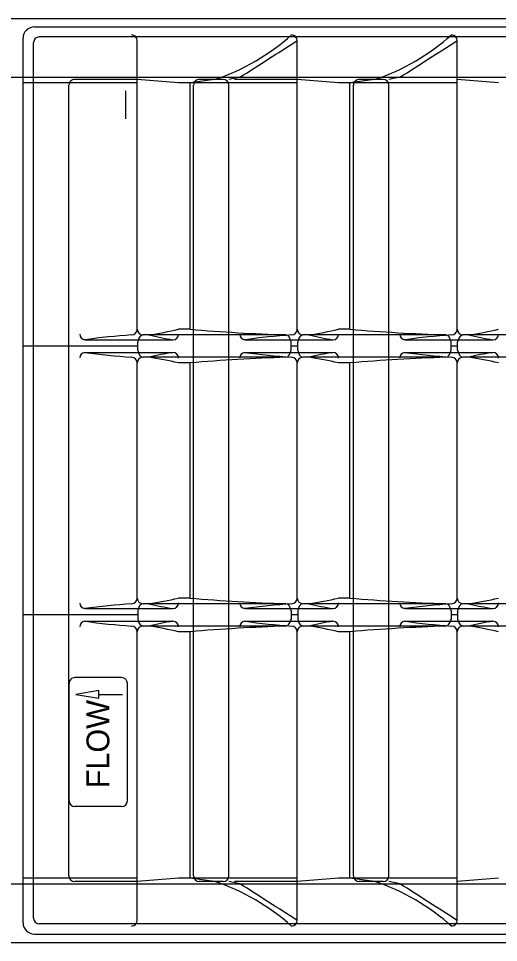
# Model space of a CAD drawing. Extents: x 0.9 to 8.1, y 0.4 to 10.5.
# Drawn here: x 4.67 to 5.041, y 9.231 to 9.946 of the extents above; entities that cross this region are included whole.
import ezdxf

# ---------------------------------------------------------------- set-up
doc = ezdxf.new("R2010")
doc.units = 0
doc.layers.add('DETL-LINE', color=7, linetype='Continuous')
doc.layers.add('DETL-NOTE', color=7, linetype='Continuous')

msp = doc.modelspace()

# ---------------------------------------------------------------- linework, layer by layer
at = {"layer": 'DETL-LINE'}
for p, q in [((3.82262, 9.94588), (5.52014, 9.94588)), ((4.68243, 9.93938), (5.51572, 9.93938)), ((4.67359, 9.24584), (4.67359, 9.93071)), ((4.68174, 9.24951), (4.68174, 9.92726)), ((5.51198, 9.93159), (4.68617, 9.93159)), ((4.762, 9.70529), (4.762, 9.92883)), ((4.88578, 9.70529), (4.88578, 9.92883)), ((5.00956, 9.70529), (5.00956, 9.92883)), ((3.86903, 9.90037), (5.47373, 9.90037)), ((4.762, 9.89868), (4.71355, 9.89868)), ((4.79394, 9.89604), (4.762, 9.89868)), ((4.82182, 9.89862), (4.80278, 9.89604)), ((4.82848, 9.89868), (4.80994, 9.89868)), ((4.84135, 9.90037), (4.8329, 9.89862)), ((4.88578, 9.89868), (4.83732, 9.89868)), ((4.91772, 9.89604), (4.88578, 9.89868)), ((4.94559, 9.89862), (4.92656, 9.89604)), ((4.95226, 9.89868), (4.93372, 9.89868)), ((4.96513, 9.90037), (4.95668, 9.89862)), ((5.0415, 9.89604), (5.00956, 9.89868)), ((4.762, 9.89604), (4.67359, 9.89604)), ((4.70913, 9.28221), (4.70913, 9.89435)), ((4.80278, 9.89604), (4.79394, 9.89604)), ((4.88578, 9.89604), (4.80278, 9.89604)), ((4.80278, 9.70531), (4.80278, 9.89604)), ((4.80552, 9.28221), (4.80552, 9.89435)), ((4.8329, 9.28221), (4.8329, 9.89435)), ((4.92656, 9.89604), (4.91772, 9.89604)), ((4.92656, 9.70531), (4.92656, 9.89604)), ((5.00956, 9.89604), (4.92656, 9.89604)), ((4.9293, 9.28221), (4.9293, 9.89435)), ((4.95668, 9.28221), (4.95668, 9.89435)), ((4.75295, 9.88992), (4.75295, 9.86809)), ((4.87694, 9.70095), (4.76642, 9.70095)), ((4.80278, 9.70531), (4.79394, 9.70531)), ((5.00072, 9.70095), (4.8902, 9.70095)), ((4.92656, 9.70531), (4.91772, 9.70531)), ((5.12449, 9.70095), (5.01398, 9.70095)), ((4.76233, 9.69231), (4.67359, 9.69231)), ((4.72136, 9.6972), (4.78952, 9.6972)), ((4.76233, 9.68906), (4.76233, 9.69556)), ((4.84514, 9.6972), (4.9133, 9.6972)), ((4.88103, 9.68906), (4.88103, 9.69556)), ((4.8861, 9.69231), (4.88103, 9.69231)), ((4.8861, 9.68906), (4.8861, 9.69556)), ((4.96892, 9.6972), (5.03708, 9.6972)), ((5.00481, 9.68906), (5.00481, 9.69556)), ((5.00988, 9.69231), (5.00481, 9.69231)), ((5.00988, 9.68906), (5.00988, 9.69556)), ((4.72136, 9.68742), (4.78952, 9.68742)), ((4.84514, 9.68742), (4.9133, 9.68742)), ((4.96892, 9.68742), (5.03708, 9.68742)), ((4.762, 9.49722), (4.762, 9.67934)), ((4.87694, 9.68367), (4.76642, 9.68367)), ((4.80278, 9.67931), (4.79394, 9.67931)), ((4.80278, 9.49725), (4.80278, 9.67931)), ((4.88578, 9.49722), (4.88578, 9.67934)), ((5.00072, 9.68367), (4.8902, 9.68367)), ((4.92656, 9.67931), (4.91772, 9.67931)), ((4.92656, 9.49725), (4.92656, 9.67931)), ((5.00956, 9.49722), (5.00956, 9.67934)), ((5.12449, 9.68367), (5.01398, 9.68367)), ((4.87694, 9.49289), (4.76642, 9.49289)), ((4.80278, 9.49725), (4.79394, 9.49725)), ((5.00072, 9.49289), (4.8902, 9.49289)), ((4.92656, 9.49725), (4.91772, 9.49725)), ((5.12449, 9.49289), (5.01398, 9.49289)), ((4.76233, 9.48425), (4.67359, 9.48425)), ((4.72136, 9.48914), (4.78952, 9.48914)), ((4.76233, 9.4875), (4.76233, 9.481)), ((4.84514, 9.48914), (4.9133, 9.48914)), ((4.88103, 9.4875), (4.88103, 9.481)), ((4.8861, 9.48425), (4.88103, 9.48425)), ((4.8861, 9.4875), (4.8861, 9.481)), ((4.96892, 9.48914), (5.03708, 9.48914)), ((5.00481, 9.4875), (5.00481, 9.481)), ((5.00988, 9.48425), (5.00481, 9.48425)), ((5.00988, 9.4875), (5.00988, 9.481)), ((4.72136, 9.47936), (4.78952, 9.47936)), ((4.84514, 9.47936), (4.9133, 9.47936)), ((4.96892, 9.47936), (5.03708, 9.47936)), ((4.762, 9.24773), (4.762, 9.47127)), ((4.87694, 9.47561), (4.76642, 9.47561)), ((4.80278, 9.47124), (4.79394, 9.47124)), ((4.80278, 9.28052), (4.80278, 9.47124)), ((4.88578, 9.24773), (4.88578, 9.47127)), ((5.00072, 9.47561), (4.8902, 9.47561)), ((4.92656, 9.47124), (4.91772, 9.47124)), ((4.92656, 9.28052), (4.92656, 9.47124)), ((5.00956, 9.24773), (5.00956, 9.47127)), ((5.12449, 9.47561), (5.01398, 9.47561)), ((4.762, 9.28052), (4.67359, 9.28052)), ((4.762, 9.27788), (4.71355, 9.27788)), ((4.79394, 9.28052), (4.762, 9.27788)), ((4.80278, 9.28052), (4.79394, 9.28052)), ((4.88578, 9.28052), (4.80278, 9.28052)), ((4.82182, 9.27794), (4.80278, 9.28052)), ((4.82848, 9.27788), (4.80994, 9.27788)), ((4.84135, 9.27619), (4.8329, 9.27794)), ((4.88578, 9.27788), (4.83732, 9.27788)), ((4.91772, 9.28052), (4.88578, 9.27788)), ((4.92656, 9.28052), (4.91772, 9.28052)), ((5.00956, 9.28052), (4.92656, 9.28052)), ((4.94559, 9.27794), (4.92656, 9.28052)), ((4.95226, 9.27788), (4.93372, 9.27788)), ((4.96513, 9.27619), (4.95668, 9.27794)), ((5.0415, 9.28052), (5.00956, 9.27788)), ((3.86903, 9.27619), (5.47373, 9.27619)), ((5.51198, 9.24517), (4.68617, 9.24517)), ((4.68243, 9.23717), (5.51572, 9.23717)), ((3.82262, 9.23067), (5.52014, 9.23067))]:
    msp.add_line(p, q, dxfattribs=at)
for centre, major_axis, ratio, start_param, end_param in [((4.68243, 9.93071), (0.00884, 0), 0.98054, 1.570796, 3.141593), ((4.68617, 9.92726), (0.00442, 0), 0.98054, 1.570796, 3.141593), ((4.75758, 9.92883), (0.00442, 0), 0.98054, 0, 1.570796), ((4.76845, 10.05367), (0.16689, 0), 0.98054, 5.037871, 5.45546), ((-5.57268, 25.57897), (19.08204, 0), 0.98054, 5.289674, 5.292455), ((4.88136, 9.92883), (0.00442, 0), 0.98054, 0, 1.570796), ((4.89223, 10.05367), (0.16689, 0), 0.98054, 5.037871, 5.45546), ((-5.4489, 25.57897), (19.08204, 0), 0.98054, 5.289674, 5.292455), ((5.00514, 9.92883), (0.00442, 0), 0.98054, 0, 1.570796), ((4.71355, 9.89435), (0.00442, 0), 0.98054, 1.570796, 3.141593), ((4.80994, 9.89435), (0.00442, 0), 0.98054, 1.570796, 3.141593), ((4.82848, 9.89435), (0.00442, 0), 0.98054, 0, 1.570796), ((4.93372, 9.89435), (0.00442, 0), 0.98054, 1.570796, 3.141593), ((4.95226, 9.89435), (0.00442, 0), 0.98054, 0, 1.570796), ((4.72199, 9.70149), (0.00442, 0), 0.98054, 3.141593, 4.569086), ((4.79758, 9.15999), (0.55314, 0), 0.98054, 1.643175, 1.709028), ((4.75758, 9.70529), (0.00442, 0), 0.98054, 4.712389, 6.283185), ((4.76642, 9.70529), (0.00442, 0), 0.98054, 3.141593, 4.712389), ((4.76642, 9.69231), (0, -0.00864), 0.511537, 3.112642, 4.326712), ((4.7212, 10.01464), (0.32374, 0), 0.98054, 4.866324, 4.938996), ((4.82826, 9.92906), (0.23962, 0), 0.98054, 4.470431, 4.550015), ((4.78952, 9.70153), (0.00442, 0), 0.98054, 4.712389, 6.283185), ((4.93221, 11.21264), (1.54268, 0), 0.98054, 4.628392, 4.676553), ((4.84577, 9.70149), (0.00442, 0), 0.98054, 3.141593, 4.569086), ((4.92136, 9.15999), (0.55314, 0), 0.98054, 1.643175, 1.709028), ((4.87694, 9.69231), (0, 0.00864), 0.511537, 5.098066, 6.283185), ((4.88136, 9.70529), (0.00442, 0), 0.98054, 4.712389, 6.283185), ((4.8902, 9.70529), (0.00442, 0), 0.98054, 3.141593, 4.712389), ((4.8902, 9.69231), (0, -0.00864), 0.511537, 3.112642, 4.326712), ((4.84498, 10.01464), (0.32374, 0), 0.98054, 4.866324, 4.938996), ((4.95204, 9.92906), (0.23962, 0), 0.98054, 4.470431, 4.550015), ((4.9133, 9.70153), (0.00442, 0), 0.98054, 4.712389, 6.283185), ((5.05599, 11.21264), (1.54268, 0), 0.98054, 4.628392, 4.676553), ((4.96955, 9.70149), (0.00442, 0), 0.98054, 3.141593, 4.569086), ((5.04514, 9.15999), (0.55314, 0), 0.98054, 1.643175, 1.709028), ((5.00072, 9.69231), (0, 0.00864), 0.511537, 5.098066, 6.283185), ((5.00514, 9.70529), (0.00442, 0), 0.98054, 4.712389, 6.283185), ((5.01398, 9.70529), (0.00442, 0), 0.98054, 3.141593, 4.712389), ((5.01398, 9.69231), (0, -0.00864), 0.511537, 3.112642, 4.326712), ((4.96876, 10.01464), (0.32374, 0), 0.98054, 4.866324, 4.938996), ((5.07581, 9.92906), (0.23962, 0), 0.98054, 4.470431, 4.550015), ((5.03708, 9.70153), (0.00442, 0), 0.98054, 4.712389, 6.283185), ((4.72199, 9.68313), (0.00442, 0), 0.98054, 1.714099, 3.141593), ((4.79758, 10.22463), (0.55314, 0), 0.98054, 4.574158, 4.64001), ((4.76642, 9.69231), (0, -0.00864), 0.511537, 5.098066, 6.283185), ((4.82826, 9.45555), (0.23962, 0), 0.98054, 1.733171, 1.812754), ((4.78952, 9.68309), (0.00442, 0), 0.98054, 0, 1.570796), ((4.84577, 9.68313), (0.00442, 0), 0.98054, 1.714099, 3.141593), ((4.92136, 10.22463), (0.55314, 0), 0.98054, 4.574158, 4.64001), ((4.87694, 9.69231), (0, 0.00864), 0.511537, 3.112642, 4.326712), ((4.8902, 9.69231), (0, -0.00864), 0.511537, 5.098066, 6.283185), ((4.95204, 9.45555), (0.23962, 0), 0.98054, 1.733171, 1.812754), ((4.9133, 9.68309), (0.00442, 0), 0.98054, 0, 1.570796), ((4.96955, 9.68313), (0.00442, 0), 0.98054, 1.714099, 3.141593), ((5.04514, 10.22463), (0.55314, 0), 0.98054, 4.574158, 4.64001), ((5.00072, 9.69231), (0, 0.00864), 0.511537, 3.112642, 4.326712), ((5.01398, 9.69231), (0, -0.00864), 0.511537, 5.098066, 6.283185), ((5.07581, 9.45555), (0.23962, 0), 0.98054, 1.733171, 1.812754), ((5.03708, 9.68309), (0.00442, 0), 0.98054, 0, 1.570796), ((4.75758, 9.67934), (0.00442, 0), 0.98054, 0, 1.570796), ((4.76642, 9.67934), (0.00442, 0), 0.98054, 1.570796, 3.141593), ((4.7212, 9.36998), (0.32374, 0), 0.98054, 1.344189, 1.416861), ((4.93221, 8.17197), (1.54268, 0), 0.98054, 1.606632, 1.654793), ((4.88136, 9.67934), (0.00442, 0), 0.98054, 0, 1.570796), ((4.8902, 9.67934), (0.00442, 0), 0.98054, 1.570796, 3.141593), ((4.84498, 9.36998), (0.32374, 0), 0.98054, 1.344189, 1.416861), ((5.05599, 8.17197), (1.54268, 0), 0.98054, 1.606632, 1.654793), ((5.00514, 9.67934), (0.00442, 0), 0.98054, 0, 1.570796), ((5.01398, 9.67934), (0.00442, 0), 0.98054, 1.570796, 3.141593), ((4.96876, 9.36998), (0.32374, 0), 0.98054, 1.344189, 1.416861), ((4.72199, 9.49343), (0.00442, 0), 0.98054, 3.141593, 4.569086), ((4.79758, 8.95193), (0.55314, 0), 0.98054, 1.643175, 1.709028), ((4.75758, 9.49722), (0.00442, 0), 0.98054, 4.712389, 6.283185), ((4.76642, 9.49722), (0.00442, 0), 0.98054, 3.141593, 4.712389), ((4.76642, 9.48425), (0, 0.00864), 0.511537, 0, 1.185119), ((4.7212, 9.80657), (0.32374, 0), 0.98054, 4.866324, 4.938996), ((4.82826, 9.721), (0.23962, 0), 0.98054, 4.470431, 4.550015), ((4.78952, 9.49347), (0.00442, 0), 0.98054, 4.712389, 6.283185), ((4.93221, 11.00458), (1.54268, 0), 0.98054, 4.628392, 4.676553), ((4.84577, 9.49343), (0.00442, 0), 0.98054, 3.141593, 4.569086), ((4.92136, 8.95193), (0.55314, 0), 0.98054, 1.643175, 1.709028), ((4.87694, 9.48425), (0, 0.00864), 0.511537, 5.098066, 6.283185), ((4.88136, 9.49722), (0.00442, 0), 0.98054, 4.712389, 6.283185), ((4.8902, 9.49722), (0.00442, 0), 0.98054, 3.141593, 4.712389), ((4.8902, 9.48425), (0, 0.00864), 0.511537, 0, 1.185119), ((4.84498, 9.80657), (0.32374, 0), 0.98054, 4.866324, 4.938996), ((4.95204, 9.721), (0.23962, 0), 0.98054, 4.470431, 4.550015), ((4.9133, 9.49347), (0.00442, 0), 0.98054, 4.712389, 6.283185), ((5.05599, 11.00458), (1.54268, 0), 0.98054, 4.628392, 4.676553), ((4.96955, 9.49343), (0.00442, 0), 0.98054, 3.141593, 4.569086), ((5.04514, 8.95193), (0.55314, 0), 0.98054, 1.643175, 1.709028), ((5.00072, 9.48425), (0, 0.00864), 0.511537, 5.098066, 6.283185), ((5.00514, 9.49722), (0.00442, 0), 0.98054, 4.712389, 6.283185), ((5.01398, 9.49722), (0.00442, 0), 0.98054, 3.141593, 4.712389), ((5.01398, 9.48425), (0, 0.00864), 0.511537, 0, 1.185119), ((4.96876, 9.80657), (0.32374, 0), 0.98054, 4.866324, 4.938996), ((5.07581, 9.721), (0.23962, 0), 0.98054, 4.470431, 4.550015), ((5.03708, 9.49347), (0.00442, 0), 0.98054, 4.712389, 6.283185), ((4.72199, 9.47507), (0.00442, 0), 0.98054, 1.714099, 3.141593), ((4.79758, 10.01657), (0.55314, 0), 0.98054, 4.574158, 4.64001), ((4.76642, 9.48425), (0, 0.00864), 0.511537, 1.956474, 3.170543), ((4.82826, 9.24749), (0.23962, 0), 0.98054, 1.733171, 1.812754), ((4.78952, 9.47502), (0.00442, 0), 0.98054, 0, 1.570796), ((4.84577, 9.47507), (0.00442, 0), 0.98054, 1.714099, 3.141593), ((4.92136, 10.01657), (0.55314, 0), 0.98054, 4.574158, 4.64001), ((4.87694, 9.48425), (0, 0.00864), 0.511537, 3.112642, 4.326712), ((4.8902, 9.48425), (0, 0.00864), 0.511537, 1.956474, 3.170543), ((4.95204, 9.24749), (0.23962, 0), 0.98054, 1.733171, 1.812754), ((4.9133, 9.47502), (0.00442, 0), 0.98054, 0, 1.570796), ((4.96955, 9.47507), (0.00442, 0), 0.98054, 1.714099, 3.141593), ((5.04514, 10.01657), (0.55314, 0), 0.98054, 4.574158, 4.64001), ((5.00072, 9.48425), (0, 0.00864), 0.511537, 3.112642, 4.326712), ((5.01398, 9.48425), (0, 0.00864), 0.511537, 1.956474, 3.170543), ((5.07581, 9.24749), (0.23962, 0), 0.98054, 1.733171, 1.812754), ((5.03708, 9.47502), (0.00442, 0), 0.98054, 0, 1.570796), ((4.75758, 9.47127), (0.00442, 0), 0.98054, 0, 1.570796), ((4.76642, 9.47127), (0.00442, 0), 0.98054, 1.570796, 3.141593), ((4.7212, 9.16192), (0.32374, 0), 0.98054, 1.344189, 1.416861), ((4.93221, 7.96391), (1.54268, 0), 0.98054, 1.606632, 1.654793), ((4.88136, 9.47127), (0.00442, 0), 0.98054, 0, 1.570796), ((4.8902, 9.47127), (0.00442, 0), 0.98054, 1.570796, 3.141593), ((4.84498, 9.16192), (0.32374, 0), 0.98054, 1.344189, 1.416861), ((5.05599, 7.96391), (1.54268, 0), 0.98054, 1.606632, 1.654793), ((5.00514, 9.47127), (0.00442, 0), 0.98054, 0, 1.570796), ((5.01398, 9.47127), (0.00442, 0), 0.98054, 1.570796, 3.141593), ((4.96876, 9.16192), (0.32374, 0), 0.98054, 1.344189, 1.416861), ((4.71355, 9.28221), (0.00442, 0), 0.98054, 3.141593, 4.712389), ((4.80994, 9.28221), (0.00442, 0), 0.98054, 3.141593, 4.712389), ((4.76845, 9.12289), (0.16689, 0), 0.98054, 0.827725, 1.245314), ((4.82848, 9.28221), (0.00442, 0), 0.98054, 4.712389, 6.283185), ((4.93372, 9.28221), (0.00442, 0), 0.98054, 3.141593, 4.712389), ((4.89223, 9.12289), (0.16689, 0), 0.98054, 0.827725, 1.245314), ((4.95226, 9.28221), (0.00442, 0), 0.98054, 4.712389, 6.283185), ((-5.57268, -6.40241), (19.08204, 0), 0.98054, 0.990731, 0.993512), ((-5.4489, -6.40241), (19.08204, 0), 0.98054, 0.990731, 0.993512), ((4.68617, 9.24951), (0.00442, 0), 0.98054, 3.141593, 4.712389), ((4.75758, 9.24773), (0.00442, 0), 0.98054, 4.712389, 6.283185), ((4.88136, 9.24773), (0.00442, 0), 0.98054, 4.712389, 6.283185), ((5.00514, 9.24773), (0.00442, 0), 0.98054, 4.712389, 6.283185), ((4.68243, 9.24584), (0.00884, 0), 0.98054, 3.141593, 4.712389)]:
    msp.add_ellipse(centre, major_axis=major_axis, ratio=ratio, start_param=start_param, end_param=end_param, dxfattribs=at)
at = {"layer": 'DETL-NOTE'}
for p, q in [((4.74988, 9.4357), (4.71363, 9.4357)), ((4.70921, 9.34026), (4.70921, 9.43137)), ((4.7543, 9.34026), (4.7543, 9.43137)), ((4.73218, 9.42273), (4.75048, 9.42273)), ((4.74988, 9.33593), (4.71363, 9.33593))]:
    msp.add_line(p, q, dxfattribs=at)
msp.add_lwpolyline([(4.73218, 9.41984), (4.73218, 9.42562), (4.7145, 9.42273)], close=True, dxfattribs=at)
for centre, start_param, end_param in [((4.71363, 9.43137), 1.570796, 3.141593), ((4.74988, 9.43137), 0, 1.570796), ((4.71363, 9.34026), 3.141593, 4.712389), ((4.74988, 9.34026), 4.712389, 6.283185)]:
    msp.add_ellipse(centre, major_axis=(0.00442, 0), ratio=0.98054, start_param=start_param, end_param=end_param, dxfattribs=at)

# ---------------------------------------------------------------- texts
msp.add_text('FLOW', height=0.017682, rotation=90, dxfattribs=at).set_placement((4.74035, 9.35008))

doc.saveas('drawing.dxf')
